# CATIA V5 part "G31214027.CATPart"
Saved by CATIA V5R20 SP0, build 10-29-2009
Part number: G31214027
Revision: 8
Definition: design
Nomenclature: G31214027
Source: made
Description: NOT SPECIFIED
Bounding box of the stored display mesh (mm): x -6 to 27, y -12.31 to 12.31, z -12.5 to 12.5
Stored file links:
  C:\Users\Raffaele\Desktop\3D X SITO CF\BOLEX\23-BUSH REF 312\G31214027.CATPart

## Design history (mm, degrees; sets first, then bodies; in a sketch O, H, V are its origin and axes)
Body1 "MANIFOLD_SOLID_BREP #7635" (main body)
  Solid1: solid without history
Body2 "MANIFOLD_SOLID_BREP #7778"
  Solid2: solid without history
Body3 "MANIFOLD_SOLID_BREP #7921"
  Solid3: solid without history
Body4 "MANIFOLD_SOLID_BREP #8064"
  Solid4: solid without history
Body5 "MANIFOLD_SOLID_BREP #8207"
  Solid5: solid without history
Body6 "MANIFOLD_SOLID_BREP #8350"
  Solid6: solid without history
Body7 "MANIFOLD_SOLID_BREP #8493"
  Solid7: solid without history
Body8 "MANIFOLD_SOLID_BREP #8638"
  Solid8: solid without history
Body9 "MANIFOLD_SOLID_BREP #8783"
  Solid9: solid without history
Body10 "MANIFOLD_SOLID_BREP #8928"
  Solid10: solid without history
Body11 "MANIFOLD_SOLID_BREP #9073"
  Solid11: solid without history
Body12 "MANIFOLD_SOLID_BREP #9216"
  Solid12: solid without history
Body13 "MANIFOLD_SOLID_BREP #9359"
  Solid13: solid without history
Body14 "MANIFOLD_SOLID_BREP #9504"
  Solid14: solid without history
Body15 "MANIFOLD_SOLID_BREP #9649"
  Solid15: solid without history
Body16 "MANIFOLD_SOLID_BREP #9794"
  Solid16: solid without history
Body17 "MANIFOLD_SOLID_BREP #9939"
  Solid17: solid without history
Body18 "MANIFOLD_SOLID_BREP #10084"
  Solid18: solid without history
Body19 "MANIFOLD_SOLID_BREP #10229"
  Solid19: solid without history
Body20 "MANIFOLD_SOLID_BREP #10374"
  Solid20: solid without history
Body21 "MANIFOLD_SOLID_BREP #10519"
  Solid21: solid without history
Body22 "MANIFOLD_SOLID_BREP #10664"
  Solid22: solid without history
Body23 "MANIFOLD_SOLID_BREP #10809"
  Solid23: solid without history
Body24 "MANIFOLD_SOLID_BREP #10954"
  Solid24: solid without history
Body25 "MANIFOLD_SOLID_BREP #11099"
  Solid25: solid without history
Body26 "MANIFOLD_SOLID_BREP #11242"
  Solid26: solid without history
Body27 "MANIFOLD_SOLID_BREP #11387"
  Solid27: solid without history
Body28 "MANIFOLD_SOLID_BREP #11532"
  Solid28: solid without history
Body29 "MANIFOLD_SOLID_BREP #11675"
  Solid29: solid without history
Body30 "MANIFOLD_SOLID_BREP #11820"
  Solid30: solid without history
Body31 "MANIFOLD_SOLID_BREP #11965"
  Solid31: solid without history
Body32 "MANIFOLD_SOLID_BREP #12108"
  Solid32: solid without history
Body33 "MANIFOLD_SOLID_BREP #12251"
  Solid33: solid without history
Body34 "MANIFOLD_SOLID_BREP #12396"
  Solid34: solid without history
Body35 "MANIFOLD_SOLID_BREP #12541"
  Solid35: solid without history
Body36 "MANIFOLD_SOLID_BREP #12686"
  Solid36: solid without history
Body37 "MANIFOLD_SOLID_BREP #12831"
  Solid37: solid without history
Body38 "MANIFOLD_SOLID_BREP #12976"
  Solid38: solid without history
Body39 "MANIFOLD_SOLID_BREP #13121"
  Solid39: solid without history
Body40 "MANIFOLD_SOLID_BREP #13266"
  Solid40: solid without history
Body41 "MANIFOLD_SOLID_BREP #13411"
  Solid41: solid without history
Body42 "MANIFOLD_SOLID_BREP #13554"
  Solid42: solid without history
Body43 "MANIFOLD_SOLID_BREP #13699"
  Solid43: solid without history
Body44 "MANIFOLD_SOLID_BREP #13844"
  Solid44: solid without history
Body45 "MANIFOLD_SOLID_BREP #13987"
  Solid45: solid without history
Body46 "MANIFOLD_SOLID_BREP #14132"
  Solid46: solid without history
Body47 "MANIFOLD_SOLID_BREP #14277"
  Solid47: solid without history
Body48 "MANIFOLD_SOLID_BREP #14422"
  Solid48: solid without history
Body49 "MANIFOLD_SOLID_BREP #14567"
  Solid49: solid without history
Body50 "MANIFOLD_SOLID_BREP #14712"
  Solid50: solid without history
Body51 "MANIFOLD_SOLID_BREP #14857"
  Solid51: solid without history
Body52 "MANIFOLD_SOLID_BREP #15002"
  Solid52: solid without history
Body53 "MANIFOLD_SOLID_BREP #15147"
  Solid53: solid without history
Body54 "MANIFOLD_SOLID_BREP #15292"
  Solid54: solid without history
Body55 "MANIFOLD_SOLID_BREP #15437"
  Solid55: solid without history
Body56 "MANIFOLD_SOLID_BREP #15580"
  Solid56: solid without history
Body57 "MANIFOLD_SOLID_BREP #15723"
  Solid57: solid without history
